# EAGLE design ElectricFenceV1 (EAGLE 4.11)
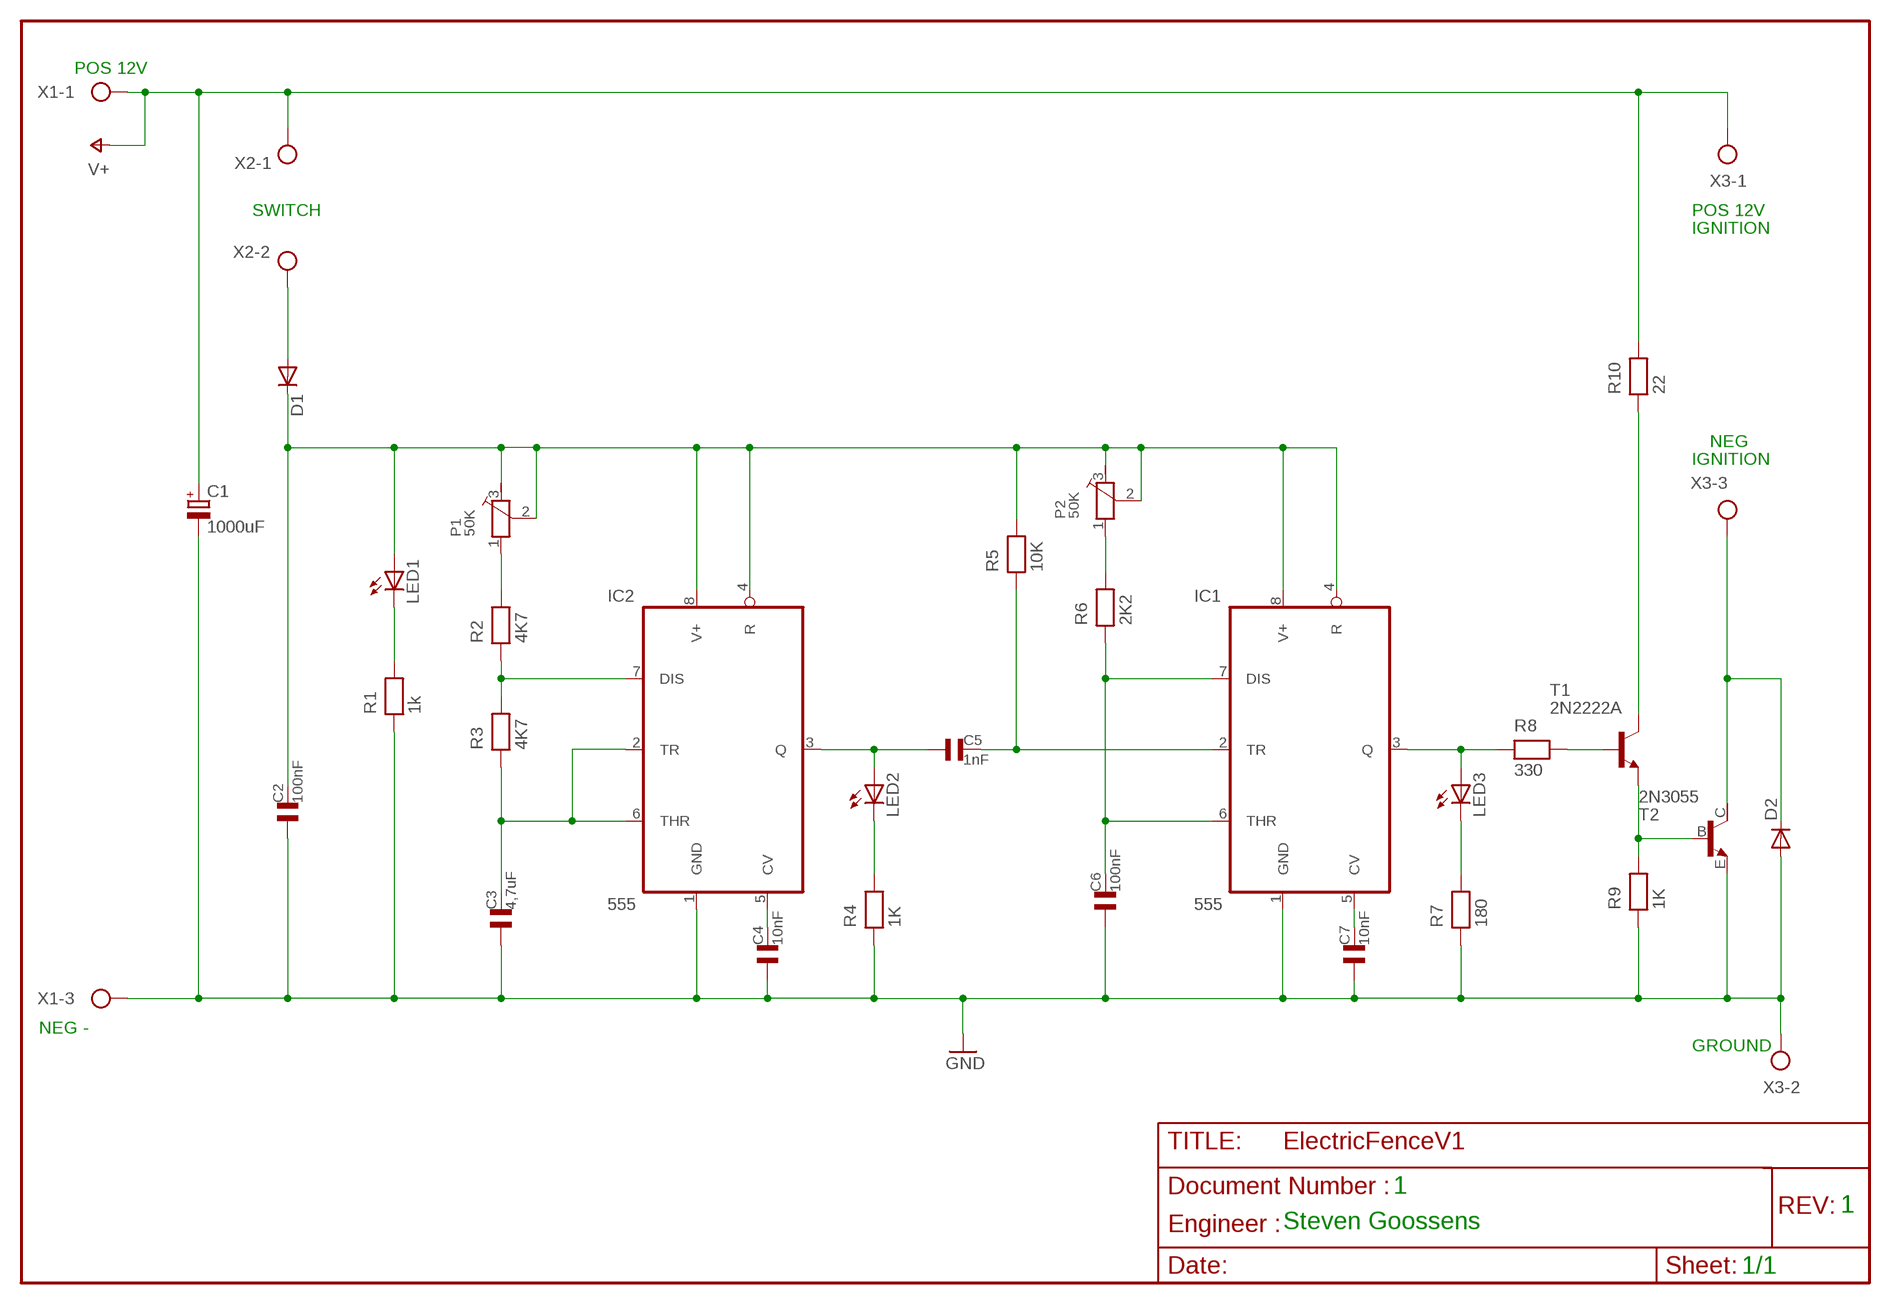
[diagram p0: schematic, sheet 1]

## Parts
C1  1000uF  CPOL-EUE7.5-16  [E7,5-16]
C2  100nF  MKT3MM-7,5MM  [C050-030X075]
C3  4,7uF  MKT8,7MM-26,8MM  [C225-087X268]
C4  10nF  MKT3MM-7,5MM  [C050-030X075]
C5  1nF  MKT3MM-7,5MM  [C050-030X075]
C6  100nF  MKT3MM-7,5MM  [C050-030X075]
C7  10nF  MKT3MM-7,5MM  [C050-030X075]
D1  1N4004LIGGEND  [DO41-10]
D2  1N4004LIGGEND  [DO41-10]
IC1  555  [DIL08]
IC2  555  [DIL08]
LED1  LED5MM  [LED5MM]
LED2  LED5MM  [LED5MM]
LED3  LED5MM  [LED5MM]
P1  50K  TRIMPOT10L  [PT10L]
P2  50K  TRIMPOT10L  [PT10L]
R1  1k  RESIST025  [R-10]
R2  4K7  RESIST025  [R-10]
R3  4K7  RESIST025  [R-10]
R4  1K  RESIST025  [R-10]
R5  10K  RESIST025  [R-10]
R6  2K2  RESIST025  [R-10]
R7  180  RESIST025  [R-10]
R8  330  RESIST025  [R-10]
R9  1K  RESIST025  [R-10]
R10  22  RESIST5W  [0617/22]
T1  2N2222A  [TO18]
T2  2N3055  [TO3]
X1  W237-103  [3PKROON]
X2  W237-102  [W237-102]
X3  W237-103  [3PKROON]

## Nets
GND: C1.- C2.1 C3.1 C4.1 C6.1 C7.1 D2.A IC1.1(GND) IC2.1(GND) R1.1 R4.1 R7.1 R9.1 T2.E X1.3 X3.2
N$1: D2.C T2.C X3.3
N$3: D1.A X2.2
N$4: C2.2 D1.C IC1.4(R) IC1.8(V+) IC2.4(R) IC2.8(V+) LED1.A P1.2 P1.3 P2.2 P2.3 R5.2
N$5: LED1.K(C) R1.2
N$6: C5.1 IC2.3(Q) LED2.A
N$7: LED2.K(C) R4.2
N$8: C6.2 IC1.6(THR) IC1.7(DIS) R6.1
N$9: P1.1 R2.2
N$10: IC2.7(DIS) R2.1 R3.2
N$11: C3.2 IC2.2(TR) IC2.6(THR) R3.1
N$12: C5.2 IC1.2(TR) R5.1
N$13: P2.1 R6.2
N$14: C4.2 IC2.5(CV)
N$15: C7.2 IC1.5(CV)
N$16: IC1.3(Q) LED3.A R8.1
N$17: LED3.K(C) R7.2
N$19: R8.2 T1.2(B)
N$20: R9.2 T1.1(E) T2.B
N$22: R10.1 T1.3(C)
V+: C1.+ R10.2 X1.1 X2.1 X3.1
Unconnected: T2.C/(C) X1.2

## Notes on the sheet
- POS 12V
- SWITCH | POS 12V
- IGNITION
- NEG
- IGNITION
- NEG -
- GROUND
- 1
- 1
- Steven Goossens
- 1/1

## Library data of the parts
C1 = rcl:CPOL-EU: POLARIZED CAPACITOR, European symbol
C2-C7 = User:MKT
D1 D2 = User:1N4004: DIODE
IC1 IC2 = User:*555: TIMER
LED1-LED3 = User:LED: LED
P1 P2 = User:TRIMPOT10L
R1-R9 = User:RESIST025
R10 = User:RESIST
T1 = User:2N2222*: NPN Transistor
T2 = transistor-npn:2N3055: NPN Transistor
X1 X3 = User:W237-103: WAGO SCREW CLAMP
X2 = User:W237-102: WAGO SCREW CLAMP

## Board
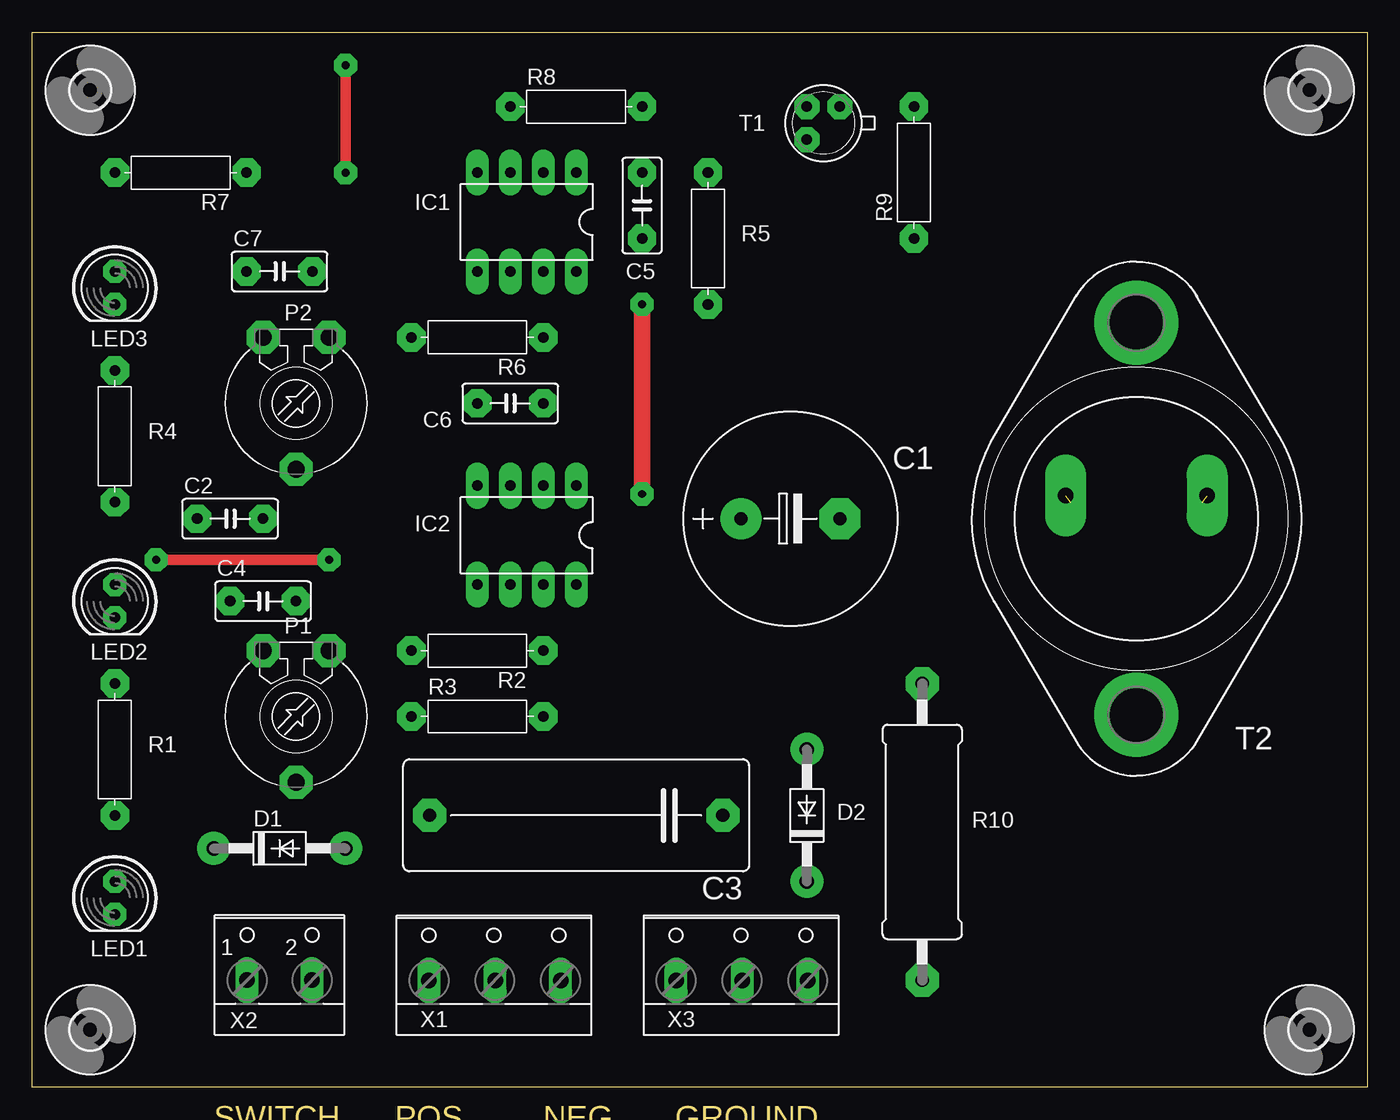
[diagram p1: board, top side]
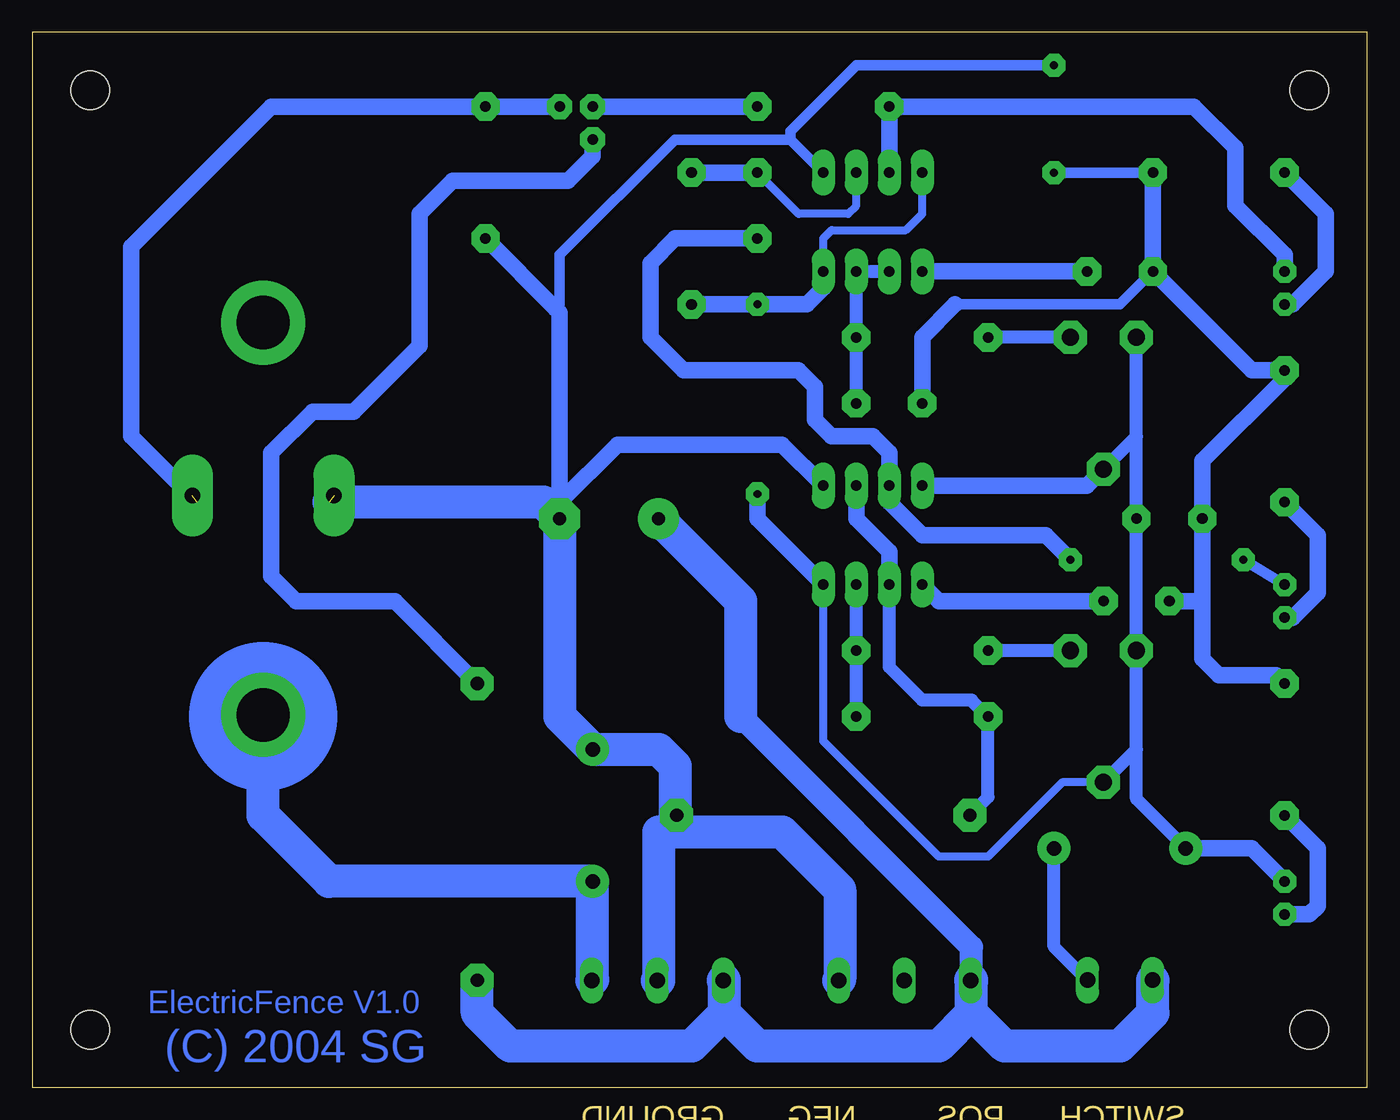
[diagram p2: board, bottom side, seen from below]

Size 102.87 x 81.28 mm. Coordinates in mm from the lower left corner, seen from the top.
Outline: 0,0.64 0,5.71
Outline: 0,5.71 0,81.28 102.87,81.28 102.87,1.27
Outline: 102.87,1.27 102.87,0.64
Outline: 102.87,1.27 102.87,0 0,0 0,5.71
Copper layers (1*16): Top 0.035mm / dielectric 1.5mm / Bottom 0.035mm
Design rules "default": minimum track width 10mil, minimum drill 24mil, track to track 8mil, track to pad 8mil, pad to pad 8mil, via to via 8mil, smd to smd 8mil, copper to edge 40mil, drill to drill 8mil, minimum pad ring 10mil, minimum via ring 8mil, stop-mask expansion 4mil, vias tented up to drill 0mil, thermal gap 10mil

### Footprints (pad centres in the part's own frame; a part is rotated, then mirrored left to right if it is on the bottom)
E7,5-16 = drill 1.016 pad 3.15 round: + -3.81,0 | drill 1.016 pad 3.15 octagon: - 3.81,0
C050-030X075 = drill 0.813 pad 2.184 octagon: 1 -2.54,0; 2 2.54,0
C225-087X268 = drill 1.016 pad 2.54 octagon: 1 -11.303,0; 2 11.303,0
DO41-10 = drill 1.118 pad 2.54 round: A 5.08,0; C -5.08,0
DIL08 = drill 0.813 pad 1.778 long: 1 -3.81,-3.81; 2 -1.27,-3.81; 3 1.27,-3.81; 4 3.81,-3.81; 5 3.81,3.81; 6 1.27,3.81; 7 -1.27,3.81; 8 -3.81,3.81
LED5MM = drill 0.813 pad 1.778 octagon: A -1.27,0; K 1.27,0
PT10L = drill 1.321 pad 2.54 octagon: 1 -2.54,-5.08; 2 0,5.08; 3 2.54,-5.08
R-10 = drill 0.813 pad 2.184 octagon: 1 -5.08,-1.27; 2 5.08,-1.27
0617/22 = drill 1.016 pad 2.54 octagon: 1 -11.43,0; 2 11.43,0
TO18 = drill 0.813 pad 1.93 octagon: 1 -1.27,-1.27; 2 1.27,-1.27; 3 1.27,1.27
TO3 = drill 1.194 pad 3.15 long: B -1.778,5.461; E -1.778,-5.461 | drill 4.115 pad 6.477 round: C 15.113,0; C/ -15.113,0
3,0 = hole 3: 0,0
3PKROON = drill 1.194 pad 1.778 long: 1 -5,-1.29 | drill 1.194 long: 2 0.1,-1.29; 3 5.16,-1.29
W237-102 = drill 1.194 long: 1 -2.5,-1.27; 2 2.5,-1.27

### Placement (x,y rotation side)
C1  58.42,43.81 0 top
C2  15.24,43.81 0 top
C3  41.91,20.96 180 top
C4  17.78,37.47 0 top
C5  46.99,67.95 90 top
C6  36.83,52.7 0 top
C7  19.05,62.87 0 top
D1  19.05,18.42 0 top
D2  59.69,20.96 90 top
IC1  38.1,66.67 180 top
IC2  38.1,42.55 180 top
LED1  6.35,14.6 270 top
LED2  6.35,37.47 270 top
LED3  6.35,61.59 270 top
P1  20.32,28.58 180 top
P2  20.32,52.7 180 top
R1  7.62,26.04 270 top
R2  34.29,32.38 180 top
R3  34.29,29.85 0 top
R4  7.62,50.16 270 top
R5  53.34,65.41 270 top
R6  34.29,56.52 180 top
R7  11.43,69.22 180 top
R8  41.91,76.84 0 top
R9  66.68,70.48 90 top
R10  68.58,19.69 270 top
T1  60.96,74.3 180 top
T2  85.09,43.81 270 top
U$2  [3,0]  4.45,76.84 0 top
U$3  [3,0]  4.45,4.45 0 top
U$4  [3,0]  98.43,4.45 0 top
U$5  [3,0]  98.43,76.84 0 top
X1  35.56,9.53 0 top
X2  19.05,9.53 0 top
X3  54.61,9.53 0 top

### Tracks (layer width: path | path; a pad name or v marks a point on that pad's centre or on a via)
GND  (via drill 0.61 pad 1.78)  (1 unrouted)
  Top 0.813: v24.13,70.48 v24.13,78.74
  Bottom 0.813: 44.45,73.03 IC1.1 | 44.45,73.03 53.34,73.03 62.23,64.13 62.23,60.33 62.55,60.01 | 31.75,60.33 19.05,60.33 C7.1 R7.1 v24.13,70.48 | v24.13,78.74 39.37,78.74 44.45,73.66 44.45,73.03
  Bottom 1.27: IC2.1 45.09,49.53 57.78,49.53 62.23,45.09 C1.- 62.23,59.69 62.55,60.01 R9.1 | R1.1 6.99,31.75 11.43,31.75 12.7,33.02 12.7,37.47 | 12.7,37.47 C2.1 12.7,48.26 6.35,54.61 R4.1 8.89,55.25 C7.1 R7.1 | C6.1 34.29,57.79 31.75,60.33 | 12.7,37.47 C4.1
  Bottom 2.54: X3.2 54.61,8.23 54.61,19.69 53.98,19.69 | 53.34,20.96 C3.1 | 53.98,19.69 53.34,19.69 53.34,20.96 | 53.34,20.96 53.34,24.77 54.61,26.04 D2.A 62.23,28.58 C1.- 63.5,45.09 80.01,45.09 | X1.3 40.64,8.31 40.64,15.24 45.09,19.69 53.98,19.69
N$1
  Bottom 2.54: X3.3 59.69,8.31 D2.C 80.01,15.88 85.09,20.96 T2.C
N$2  (via drill 0.61 pad 1.78)
  other vias: 46.99,60.33
N$3
  Bottom 1.016: X2.2 24.13,10.83 D1.A
N$4  (via drill 0.61 pad 1.78)
  Top 1.27: v46.99,45.72 v46.99,60.33
  Bottom 0.61: IC1.8 41.91,65.41 41.27,66.04 35.56,66.04 34.29,67.31 IC1.4 | IC2.8 41.91,26.67 33.02,17.78 29.21,17.78 23.49,23.5 P1.2
  Bottom 1.016: 17.78,50.16 P2.2 | 17.78,50.16 P2.3 | 17.78,26.04 P1.2 | 17.78,26.04 P1.3 C2.2 17.78,50.16 | D1.C 17.78,22.23 17.78,26.04
  Bottom 1.27: IC2.4 21.59,46.36 P2.2 | LED1.A 8.89,18.42 D1.C | IC1.8 41.91,61.59 43.18,60.33 v46.99,60.33 R5.2 | v46.99,45.72 46.99,43.81 IC2.8
N$5
  Bottom 1.27: R1.2 3.81,18.42 3.81,13.97 4.45,13.33 LED1.K
N$6  (via drill 0.61 pad 1.78)
  Top 0.813: v9.53,40.64 v22.86,40.64
  Bottom 0.813: 36.83,45.09 IC2.3 | LED2.A v9.53,40.64
  Bottom 1.27: C5.1 53.34,65.41 55.24,63.5 55.24,57.79 52.7,55.25 43.81,55.25 42.55,53.98 42.55,51.44 41.27,50.16 38.1,50.16 36.83,48.9 IC2.3 | 36.83,45.09 34.29,42.55 24.77,42.55 v22.86,40.64
N$7
  Bottom 1.27: R4.2 3.81,42.55 3.81,38.1 5.71,36.2 LED2.K
N$8
  Bottom 1.016: C6.2 R6.1 IC1.7 IC1.6
N$9
  Bottom 1.016: P1.1 R2.2
N$10
  Bottom 1.016: IC2.7 R2.1 R3.2
N$11
  Bottom 1.016: C3.2 29.21,22.35 R3.1 30.48,29.85 34.29,29.85 36.83,32.38 IC2.6
  Bottom 1.27: IC2.6 36.83,41.27 39.37,43.81 IC2.2
N$12
  Bottom 0.61: C5.2 43.81,67.31 40.01,67.31 39.37,67.95 IC1.2
  Bottom 1.27: C5.2 R5.1
N$13
  Bottom 1.016: P2.1 R6.2
N$14
  Bottom 1.27: C4.2 33.02,37.47 IC2.5
N$15
  Bottom 1.27: C7.2 IC1.5
N$16
  Bottom 1.27: IC1.3 R8.1 13.34,75.56 10.16,72.39 10.16,67.95 6.35,64.13 LED3.A
N$17
  Bottom 1.27: R7.2 3.17,67.31 3.17,62.87 5.71,60.33 LED3.K
N$18  (via drill 0.61 pad 1.78)
  other vias: 46.99,45.72
N$19
  Bottom 1.27: R8.2 T1.2
N$20  (1 unrouted)
  Bottom 1.27: T1.1 R9.2 84.46,75.56 95.25,64.77 95.25,50.16 90.17,45.09
N$21  (via drill 0.61 pad 1.78)
  other vias: 22.86,40.64
N$22
  Bottom 1.27: R10.1 74.93,37.47 82.55,37.47 84.46,39.37 84.46,48.9 81.28,52.07 78.11,52.07 73.03,57.15 73.03,67.31 70.48,69.85 61.59,69.85 59.69,71.75 T1.3
N$23  (via drill 0.61 pad 1.78)
  other vias: 9.53,40.64
N$24  (via drill 0.61 pad 1.78)
  other vias: 24.13,70.48
N$25  (via drill 0.61 pad 1.78)
  other vias: 24.13,78.74
N$26
  Bottom 2.184: 84.46,24.77 83.82,24.77 82.55,26.04 82.55,26.67 81.28,27.94 81.28,29.85 83.82,32.38 86.36,32.38 87.63,31.12 87.63,30.48 88.9,29.21 88.9,27.94 87,26.04 86.36,26.04 85.73,25.4 85.73,24.77
V+
  Bottom 1.778: 30.48,8.25 30.48,10.79 48.26,28.58
  Bottom 2.54: X2.1 16.51,8.21 16.51,5.71 19.05,3.17 27.94,3.17 30.48,5.71 | 30.48,5.71 30.48,8.25 30.54,8.25 X1.1 30.48,8.15 30.48,5.71 | 30.48,5.71 33.02,3.17 46.99,3.17 49.53,5.71 | 49.53,5.71 49.53,8.25 49.59,8.25 X3.1 49.53,8.15 49.53,5.71 | 49.53,5.71 52.07,3.17 66.04,3.17 68.58,5.71 R10.2 | C1.+ 48.26,37.47 48.26,29.21 48.26,28.58
(copper drawn outside any net)
  shapes: Bottom circle x1

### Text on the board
Bottom: ElectricFence V1.0 | (C) 2004 SG
Dimension: SWITCH | POS | NEG | GROUND | IGN + | IGN -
